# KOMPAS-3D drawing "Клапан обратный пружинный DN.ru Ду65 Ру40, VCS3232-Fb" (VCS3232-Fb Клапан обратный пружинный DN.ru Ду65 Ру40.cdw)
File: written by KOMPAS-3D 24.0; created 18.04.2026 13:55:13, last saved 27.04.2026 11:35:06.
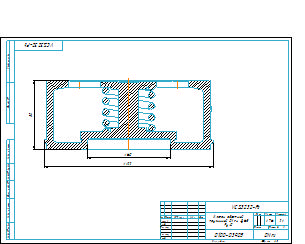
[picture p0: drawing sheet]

Document properties: c3d_UniqueCompID: 071bd168-1a06-425c-849c-e99e84a96128; Наименование: Деталь; Автор: 712; Класс точности: c; Знак неуказанной шероховатости: Шероховатость не задана; Рассекать на разрезах: Да; c3d_UniqueCompID: 071bd168-1a06-425c-849c-e99e84a96128; Наименование: Деталь; Автор: 712; Класс точности: c; Знак неуказанной шероховатости: Шероховатость не задана; Рассекать на разрезах: Да; c3d_UniqueCompID: 071bd168-1a06-425c-849c-e99e84a96128; Наименование: Деталь; Автор: 712; Класс точности: c; Знак неуказанной шероховатости: Шероховатость не задана; Рассекать на разрезах: Да; c3d_UniqueCompID: 071bd168-1a06-425c-849c-e99e84a96128; Наименование: Деталь; Автор: 712; Класс точности: c; Знак неуказанной шероховатости: Шероховатость не задана; Рассекать на разрезах: Да; c3d_UniqueCompID: 071bd168-1a06-425c-849c-e99e84a96128; Наименование: Деталь; Автор: 712; Класс точности: c; Знак неуказанной шероховатости: Шероховатость не задана; Рассекать на разрезах: Да; c3d_UniqueCompID: 071bd168-1a06-425c-849c-e99e84a96128; Наименование: Деталь; Автор: 712; Класс точности: c; Знак неуказанной шероховатости: Шероховатость не задана; Рассекать на разрезах: Да; c3d_UniqueCompID: 071bd168-1a06-425c-849c-e99e84a96128; Наименование: Деталь; Автор: 712; Класс точности: c; Знак неуказанной шероховатости: Шероховатость не задана; Рассекать на разрезах: Да; Автор: 712; Форматы листов документа: A3; Полное имя файла: VCS3232-Fb Клапан обратный пружинный DN.ru Ду65 Ру40.m3d; Масса: 1.76; Наименование: Клапан обратный пружинный DN.ru Ду65 Ру40; Количество листов документа: 1; Примечание: D100-03905

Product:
- Component: Пружина 1086-0916 ГОСТ 18793-80  | qty 1  | additional columns: 3953604318-4147491677-0; Деталь; Пользователь Windows; c; Шероховатость не задана; Да; Сталь 10  ГОСТ 1050-88; source file: Деталь_4.m3d
- Body: Тело 1  | qty 1
    Масса: 1.486414
- Part/product: Клапан обратный пружинный DN.ru Ду65 Ру40  | designation VCS3232-Fb
    Масса: 1.76
    Раздел спецификации: Прочие изделия
    Примечание: D100-03905
    additional columns: 071bd168-1a06-425c-849c-e99e84a96128; Деталь; 712; c; Шероховатость не задана; Да

Views: Вид 1, Местный разрез 1, Спереди
Referenced files in C:\Users\712\Desktop\Новая папка (4)\: VCS3232-Fb Клапан обратный пружинный DN.ru Ду15 Ру40.m3d, VCS3232-Fb Клапан обратный пружинный DN.ru Ду65 Ру40.m3d, VCS3232-Fb Клапан обратный пружинный DN.ru Ду15 Ру40.cdw
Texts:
  VCS3232-Fb
  Клапан обратный
  пружинный DN.ru Ду65
  Ру40
  Клапан обратный пружинный DN.ru Ду65 Ру40
  VCS3232-Fb Клапан обратный пружинный DN.ru Ду65 Ру40
Dimensions and other numbers on the sheet: 0; 3; 2; 4; 122; 60; 50; 2:1; 1; 1,76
